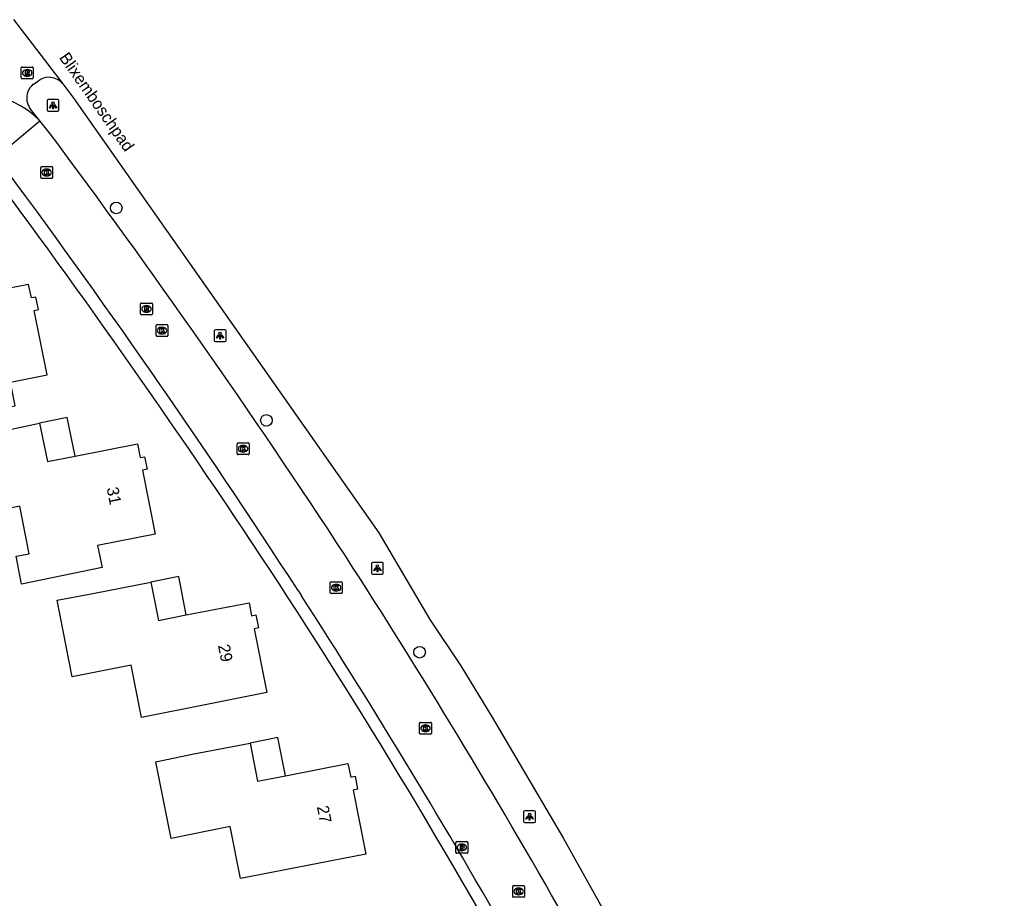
# Model space of a CAD drawing. Extents: x 159628 to 160723, y 388176 to 389416.
# Drawn here: x 160613.8 to 160696.7, y 388586.9 to 388661.2 of the extents above; entities that cross this region are included whole.
import ezdxf

# ---------------------------------------------------------------- set-up
doc = ezdxf.new("R2010")
doc.units = 0
for name, color, linetype in [('IMGEO_Boom', 7, 'Continuous'), ('IMGEO_Brandkraan', 7, 'Continuous'), ('IMGEO_Fietspad_gesloten', 7, 'Continuous'), ('IMGEO_Fietspad_open', 7, 'Continuous'), ('IMGEO_Kolk', 7, 'Continuous'), ('IMGEO_Lichtpunt', 7, 'Continuous'), ('IMGEO_Openbare_ruimte_label', 7, 'Continuous'), ('IMGEO_Pand', 7, 'Continuous'), ('IMGEO_Pand_nummerreeks', 7, 'Continuous'), ('IMGEO_Pand_overbouw', 7, 'Continuous'), ('IMGEO_Rijbaan_lokaal_open', 7, 'Continuous'), ('IMGEO_Rioolput', 7, 'Continuous'), ('IMGEO_Voetpad_open', 7, 'Continuous')]:
    doc.layers.add(name, color=color, linetype=linetype)

msp = doc.modelspace()

# ---------------------------------------------------------------- linework, layer by layer
at = {"layer": 'IMGEO_Boom'}
for centre in [(160621.931, 388645.272), (160634.62, 388627.316), (160647.568, 388607.711)]:
    msp.add_circle(centre, 0.489, dxfattribs=at)
at = {"layer": 'IMGEO_Brandkraan'}
for p, q in [((160650.633, 388590.785), (160650.633, 388591.637)), ((160650.708, 388591.711), (160651.56, 388591.711)), ((160651.634, 388591.637), (160651.634, 388590.785)), ((160651.144, 388590.931), (160651.119, 388590.931)), ((160651.121, 388591.491), (160651.146, 388591.491)), ((160651.56, 388590.711), (160650.708, 388590.711))]:
    msp.add_line(p, q, dxfattribs=at)
for points in [[(160650.633, 388590.785), (160650.633, 388591.637)], [(160650.708, 388591.711), (160651.56, 388591.711)], [(160651.634, 388591.637), (160651.634, 388590.785)], [(160650.981, 388591.411), (160650.981, 388591.011), (160651.194, 388591.011)], [(160651.212, 388591.411), (160650.981, 388591.411)], [(160651.16, 388591.33), (160651.106, 388591.33), (160651.106, 388591.254)], [(160651.106, 388591.254), (160651.159, 388591.254)], [(160651.168, 388591.178), (160651.106, 388591.178), (160651.106, 388591.097)], [(160651.106, 388591.097), (160651.168, 388591.097)], [(160651.56, 388590.711), (160650.708, 388590.711)]]:
    msp.add_lwpolyline(points, dxfattribs=at)
for centre, radius, start, end in [((160650.71, 388591.635), 0.0765, 91.55205, 178.44795), ((160650.71, 388591.635), 0.0765, 91.55205, 178.44795), ((160651.558, 388591.635), 0.0765, 1.55205, 88.44795), ((160651.558, 388591.635), 0.0765, 1.55205, 88.44795), ((160651.161, 388591.292), 0.0379, 267.82845, 90.93552), ((160651.169, 388591.137), 0.0404, 269.87594, 90.50774), ((160651.2, 388591.262), 0.251, 268.66757, 293.53466), ((160651.216, 388591.266), 0.145, 59.4692, 91.53667), ((160651.241, 388591.313), 0.0922, 285.51372, 58.15012), ((160651.246, 388591.121), 0.105, 301.31148, 78.98903), ((160650.71, 388590.787), 0.0765, 181.55205, 268.44795), ((160650.71, 388590.787), 0.0765, 181.55205, 268.44795), ((160651.558, 388590.787), 0.0765, 271.55205, 358.44795), ((160651.558, 388590.787), 0.0765, 271.55205, 358.44795)]:
    msp.add_arc(centre, radius, start, end, dxfattribs=at)
for centre, major_axis, ratio, start_param, end_param in [((160651.12, 388591.211), (-0.387, 0.002), 0.722429, 4.712389, 7.853982), ((160651.145, 388591.211), (-0.39, 0.002), 0.717154, 1.570796, 4.712389)]:
    msp.add_ellipse(centre, major_axis=major_axis, ratio=ratio, start_param=start_param, end_param=end_param, dxfattribs=at)
at = {"layer": 'IMGEO_Fietspad_gesloten'}
for points in [[(160613.259, 388661.194), (160617.404, 388655.77)], [(160617.404, 388655.77), (160618.348, 388654.532), (160644.11, 388617.805), (160648.439, 388610.479), (160651.047, 388606.571), (160653.72, 388602.158), (160659.741, 388591.966), (160665.707, 388581.259), (160668.575, 388576.406), (160671.137, 388571.605), (160689.88, 388531.792), (160696.248, 388516.722), (160696.73, 388515.639)]]:
    msp.add_lwpolyline(points, dxfattribs=at)
at = {"layer": 'IMGEO_Fietspad_open'}
for points in [[(160614.945, 388655.743), (160615.331, 388656.003)], [(160615.474, 388652.64), (160614.696, 388653.623)]]:
    msp.add_lwpolyline(points, dxfattribs=at)
for centre, radius, start, end in [((160615.852, 388654.562), 1.489, 127.52045, 219.08183), ((160616.249, 388654.833), 1.487, 39.04601, 128.12802)]:
    msp.add_arc(centre, radius, start, end, dxfattribs=at)
at = {"layer": 'IMGEO_Kolk'}
for p, q in [((160615.552, 388647.844), (160615.552, 388648.696)), ((160615.627, 388648.77), (160616.479, 388648.77)), ((160616.04, 388648.55), (160616.065, 388648.55)), ((160616.553, 388648.696), (160616.553, 388647.844)), ((160616.479, 388647.77), (160615.627, 388647.77)), ((160616.063, 388647.99), (160616.038, 388647.99)), ((160625.297, 388634.482), (160625.297, 388635.334)), ((160625.372, 388635.408), (160626.224, 388635.408)), ((160625.785, 388635.188), (160625.81, 388635.188)), ((160626.298, 388635.334), (160626.298, 388634.482)), ((160626.224, 388634.408), (160625.372, 388634.408)), ((160625.808, 388634.628), (160625.783, 388634.628)), ((160632.149, 388624.488), (160632.149, 388625.34)), ((160632.224, 388625.414), (160633.076, 388625.414)), ((160632.637, 388625.194), (160632.662, 388625.194)), ((160633.15, 388625.34), (160633.15, 388624.488)), ((160633.076, 388624.414), (160632.224, 388624.414)), ((160632.66, 388624.634), (160632.635, 388624.634)), ((160640.021, 388612.744), (160640.021, 388613.596)), ((160640.096, 388613.67), (160640.948, 388613.67)), ((160640.509, 388613.45), (160640.534, 388613.45)), ((160641.022, 388613.596), (160641.022, 388612.744)), ((160640.948, 388612.67), (160640.096, 388612.67)), ((160640.532, 388612.89), (160640.507, 388612.89)), ((160647.562, 388600.854), (160647.562, 388601.706)), ((160647.637, 388601.78), (160648.489, 388601.78)), ((160648.563, 388601.706), (160648.563, 388600.854)), ((160648.489, 388600.78), (160647.637, 388600.78)), ((160648.073, 388601), (160648.048, 388601)), ((160648.05, 388601.56), (160648.075, 388601.56)), ((160655.434, 388587.066), (160655.434, 388587.918)), ((160655.509, 388587.992), (160656.361, 388587.992)), ((160655.922, 388587.772), (160655.947, 388587.772)), ((160656.435, 388587.918), (160656.435, 388587.066)), ((160656.361, 388586.992), (160655.509, 388586.992)), ((160655.945, 388587.212), (160655.92, 388587.212))]:
    msp.add_line(p, q, dxfattribs=at)
for points in [[(160615.552, 388647.844), (160615.552, 388648.696)], [(160615.627, 388648.77), (160616.479, 388648.77)], [(160615.873, 388648.47), (160615.996, 388648.47), (160615.996, 388648.319), (160616.126, 388648.47), (160616.29, 388648.47), (160616.144, 388648.319), (160616.297, 388648.07), (160616.145, 388648.07), (160616.06, 388648.234), (160615.996, 388648.167), (160615.996, 388648.07), (160615.873, 388648.07), (160615.873, 388648.47)], [(160616.553, 388648.696), (160616.553, 388647.844)], [(160616.479, 388647.77), (160615.627, 388647.77)], [(160625.297, 388634.482), (160625.297, 388635.334)], [(160625.372, 388635.408), (160626.224, 388635.408)], [(160625.618, 388635.108), (160625.741, 388635.108), (160625.741, 388634.957), (160625.871, 388635.108), (160626.035, 388635.108), (160625.889, 388634.957), (160626.042, 388634.708), (160625.89, 388634.708), (160625.805, 388634.872), (160625.741, 388634.805), (160625.741, 388634.708), (160625.618, 388634.708), (160625.618, 388635.108)], [(160626.298, 388635.334), (160626.298, 388634.482)], [(160626.224, 388634.408), (160625.372, 388634.408)], [(160632.149, 388624.488), (160632.149, 388625.34)], [(160632.224, 388625.414), (160633.076, 388625.414)], [(160632.47, 388625.114), (160632.593, 388625.114), (160632.593, 388624.963), (160632.723, 388625.114), (160632.887, 388625.114), (160632.741, 388624.963), (160632.894, 388624.714), (160632.742, 388624.714), (160632.657, 388624.878), (160632.593, 388624.811), (160632.593, 388624.714), (160632.47, 388624.714), (160632.47, 388625.114)], [(160633.15, 388625.34), (160633.15, 388624.488)], [(160633.076, 388624.414), (160632.224, 388624.414)], [(160640.021, 388612.744), (160640.021, 388613.596)], [(160640.096, 388613.67), (160640.948, 388613.67)], [(160640.342, 388613.37), (160640.465, 388613.37), (160640.465, 388613.219), (160640.595, 388613.37), (160640.759, 388613.37), (160640.613, 388613.219), (160640.766, 388612.97), (160640.614, 388612.97), (160640.529, 388613.134), (160640.465, 388613.067), (160640.465, 388612.97), (160640.342, 388612.97), (160640.342, 388613.37)], [(160641.022, 388613.596), (160641.022, 388612.744)], [(160640.948, 388612.67), (160640.096, 388612.67)], [(160647.562, 388600.854), (160647.562, 388601.706)], [(160647.637, 388601.78), (160648.489, 388601.78)], [(160648.563, 388601.706), (160648.563, 388600.854)], [(160648.489, 388600.78), (160647.637, 388600.78)], [(160647.883, 388601.48), (160648.006, 388601.48), (160648.006, 388601.329), (160648.136, 388601.48), (160648.3, 388601.48), (160648.154, 388601.329), (160648.307, 388601.08), (160648.155, 388601.08), (160648.07, 388601.244), (160648.006, 388601.177), (160648.006, 388601.08), (160647.883, 388601.08), (160647.883, 388601.48)], [(160655.434, 388587.066), (160655.434, 388587.918)], [(160655.509, 388587.992), (160656.361, 388587.992)], [(160655.755, 388587.692), (160655.878, 388587.692), (160655.878, 388587.541), (160656.008, 388587.692), (160656.172, 388587.692), (160656.026, 388587.541), (160656.179, 388587.292), (160656.027, 388587.292), (160655.942, 388587.456), (160655.878, 388587.389), (160655.878, 388587.292), (160655.755, 388587.292), (160655.755, 388587.692)], [(160656.435, 388587.918), (160656.435, 388587.066)], [(160656.361, 388586.992), (160655.509, 388586.992)]]:
    msp.add_lwpolyline(points, dxfattribs=at)
for centre, start, end in [((160615.629, 388648.694), 91.55205, 178.44795), ((160615.629, 388648.694), 91.55205, 178.44795), ((160616.477, 388648.694), 1.55205, 88.44795), ((160616.477, 388648.694), 1.55205, 88.44795), ((160615.629, 388647.846), 181.55205, 268.44795), ((160615.629, 388647.846), 181.55205, 268.44795), ((160616.477, 388647.846), 271.55205, 358.44795), ((160616.477, 388647.846), 271.55205, 358.44795), ((160625.374, 388635.332), 91.55205, 178.44795), ((160625.374, 388635.332), 91.55205, 178.44795), ((160626.222, 388635.332), 1.55205, 88.44795), ((160626.222, 388635.332), 1.55205, 88.44795), ((160625.374, 388634.484), 181.55205, 268.44795), ((160625.374, 388634.484), 181.55205, 268.44795), ((160626.222, 388634.484), 271.55205, 358.44795), ((160626.222, 388634.484), 271.55205, 358.44795), ((160632.226, 388625.338), 91.55205, 178.44795), ((160632.226, 388625.338), 91.55205, 178.44795), ((160633.074, 388625.338), 1.55205, 88.44795), ((160633.074, 388625.338), 1.55205, 88.44795), ((160632.226, 388624.49), 181.55205, 268.44795), ((160632.226, 388624.49), 181.55205, 268.44795), ((160633.074, 388624.49), 271.55205, 358.44795), ((160633.074, 388624.49), 271.55205, 358.44795), ((160640.098, 388613.594), 91.55205, 178.44795), ((160640.098, 388613.594), 91.55205, 178.44795), ((160640.946, 388613.594), 1.55205, 88.44795), ((160640.946, 388613.594), 1.55205, 88.44795), ((160640.098, 388612.746), 181.55205, 268.44795), ((160640.098, 388612.746), 181.55205, 268.44795), ((160640.946, 388612.746), 271.55205, 358.44795), ((160640.946, 388612.746), 271.55205, 358.44795), ((160647.639, 388601.704), 91.55205, 178.44795), ((160647.639, 388601.704), 91.55205, 178.44795), ((160648.487, 388601.704), 1.55205, 88.44795), ((160648.487, 388601.704), 1.55205, 88.44795), ((160647.639, 388600.856), 181.55205, 268.44795), ((160647.639, 388600.856), 181.55205, 268.44795), ((160648.487, 388600.856), 271.55205, 358.44795), ((160648.487, 388600.856), 271.55205, 358.44795), ((160655.511, 388587.916), 91.55205, 178.44795), ((160655.511, 388587.916), 91.55205, 178.44795), ((160656.359, 388587.916), 1.55205, 88.44795), ((160656.359, 388587.916), 1.55205, 88.44795), ((160655.511, 388587.068), 181.55205, 268.44795), ((160655.511, 388587.068), 181.55205, 268.44795), ((160656.359, 388587.068), 271.55205, 358.44795), ((160656.359, 388587.068), 271.55205, 358.44795)]:
    msp.add_arc(centre, 0.0765, start, end, dxfattribs=at)
for centre, major_axis, ratio, start_param, end_param in [((160616.039, 388648.27), (-0.387, 0.002), 0.722429, 4.712389, 7.853982), ((160616.064, 388648.27), (-0.39, 0.002), 0.717154, 1.570796, 4.712389), ((160625.784, 388634.908), (-0.387, 0.002), 0.722429, 4.712389, 7.853982), ((160625.809, 388634.908), (-0.39, 0.002), 0.717154, 1.570796, 4.712389), ((160632.636, 388624.914), (-0.387, 0.002), 0.722429, 4.712389, 7.853982), ((160632.661, 388624.914), (-0.39, 0.002), 0.717154, 1.570796, 4.712389), ((160640.508, 388613.17), (-0.387, 0.002), 0.722429, 4.712389, 7.853982), ((160640.533, 388613.17), (-0.39, 0.002), 0.717154, 1.570796, 4.712389), ((160648.049, 388601.28), (-0.387, 0.002), 0.722429, 4.712389, 7.853982), ((160648.074, 388601.28), (-0.39, 0.002), 0.717154, 1.570796, 4.712389), ((160655.921, 388587.492), (-0.387, 0.002), 0.722429, 4.712389, 7.853982), ((160655.946, 388587.492), (-0.39, 0.002), 0.717154, 1.570796, 4.712389)]:
    msp.add_ellipse(centre, major_axis=major_axis, ratio=ratio, start_param=start_param, end_param=end_param, dxfattribs=at)
at = {"layer": 'IMGEO_Lichtpunt'}
for p, q in [((160616.093, 388654.344), (160616.093, 388653.537)), ((160616.093, 388654.344), (160616.093, 388653.537)), ((160616.995, 388654.439), (160616.187, 388654.439)), ((160616.995, 388654.439), (160616.187, 388654.439)), ((160617.089, 388653.537), (160617.089, 388654.344)), ((160617.089, 388653.537), (160617.089, 388654.344)), ((160616.187, 388653.443), (160616.995, 388653.443)), ((160616.187, 388653.443), (160616.995, 388653.443)), ((160630.212, 388634.884), (160630.212, 388634.077)), ((160630.212, 388634.884), (160630.212, 388634.077)), ((160631.114, 388634.979), (160630.306, 388634.979)), ((160631.114, 388634.979), (160630.306, 388634.979)), ((160631.208, 388634.077), (160631.208, 388634.884)), ((160631.208, 388634.077), (160631.208, 388634.884)), ((160630.306, 388633.983), (160631.114, 388633.983)), ((160630.306, 388633.983), (160631.114, 388633.983)), ((160643.505, 388615.206), (160643.505, 388614.399)), ((160643.505, 388615.206), (160643.505, 388614.399)), ((160644.407, 388615.301), (160643.599, 388615.301)), ((160644.407, 388615.301), (160643.599, 388615.301)), ((160644.501, 388614.399), (160644.501, 388615.206)), ((160644.501, 388614.399), (160644.501, 388615.206)), ((160643.599, 388614.305), (160644.407, 388614.305)), ((160643.599, 388614.305), (160644.407, 388614.305)), ((160656.359, 388594.213), (160656.359, 388593.406)), ((160656.359, 388594.213), (160656.359, 388593.406)), ((160657.261, 388594.308), (160656.453, 388594.308)), ((160657.261, 388594.308), (160656.453, 388594.308)), ((160657.355, 388593.406), (160657.355, 388594.213)), ((160657.355, 388593.406), (160657.355, 388594.213)), ((160656.453, 388593.312), (160657.261, 388593.312)), ((160656.453, 388593.312), (160657.261, 388593.312))]:
    msp.add_line(p, q, dxfattribs=at)
for points in [[(160616.467, 388654.008), (160616.506, 388653.98), (160616.318, 388653.718), (160616.28, 388653.745), (160616.467, 388654.008)], [(160616.569, 388653.96), (160616.616, 388653.96), (160616.616, 388653.638), (160616.569, 388653.638), (160616.569, 388653.96)], [(160616.679, 388653.98), (160616.717, 388654.007), (160616.904, 388653.745), (160616.865, 388653.717), (160616.679, 388653.98)], [(160630.586, 388634.548), (160630.625, 388634.52), (160630.437, 388634.258), (160630.399, 388634.285), (160630.586, 388634.548)], [(160630.688, 388634.5), (160630.735, 388634.5), (160630.735, 388634.178), (160630.688, 388634.178), (160630.688, 388634.5)], [(160630.798, 388634.52), (160630.836, 388634.547), (160631.023, 388634.285), (160630.984, 388634.257), (160630.798, 388634.52)], [(160643.879, 388614.87), (160643.918, 388614.842), (160643.73, 388614.58), (160643.692, 388614.607), (160643.879, 388614.87)], [(160644.091, 388614.842), (160644.129, 388614.869), (160644.316, 388614.607), (160644.277, 388614.579), (160644.091, 388614.842)], [(160643.981, 388614.822), (160644.028, 388614.822), (160644.028, 388614.5), (160643.981, 388614.5), (160643.981, 388614.822)], [(160656.733, 388593.877), (160656.772, 388593.849), (160656.584, 388593.587), (160656.546, 388593.614), (160656.733, 388593.877)], [(160656.835, 388593.829), (160656.882, 388593.829), (160656.882, 388593.507), (160656.835, 388593.507), (160656.835, 388593.829)], [(160656.945, 388593.849), (160656.983, 388593.876), (160657.17, 388593.614), (160657.131, 388593.586), (160656.945, 388593.849)]]:
    msp.add_lwpolyline(points, dxfattribs=at)
for centre in [(160616.592, 388654.142), (160630.711, 388634.682), (160644.004, 388615.004), (160656.858, 388594.011)]:
    msp.add_circle(centre, 0.0994, dxfattribs=at)
for centre, start, end in [((160616.187, 388654.344), 90, 180), ((160616.187, 388654.344), 90, 180), ((160616.995, 388654.344), 0, 90), ((160616.995, 388654.344), 0, 90), ((160616.187, 388653.537), 180, 270), ((160616.187, 388653.537), 180, 270), ((160616.995, 388653.537), 270, 0), ((160616.995, 388653.537), 270, 360), ((160630.306, 388634.884), 90, 180), ((160630.306, 388634.884), 90, 180), ((160631.114, 388634.884), 0, 90), ((160631.114, 388634.884), 0, 90), ((160630.306, 388634.077), 180, 270), ((160630.306, 388634.077), 180, 270), ((160631.114, 388634.077), 270, 0), ((160631.114, 388634.077), 270, 360), ((160643.599, 388615.206), 90, 180), ((160643.599, 388615.206), 90, 180), ((160644.407, 388615.206), 0, 90), ((160644.407, 388615.206), 0, 90), ((160643.599, 388614.399), 180, 270), ((160643.599, 388614.399), 180, 270), ((160644.407, 388614.399), 270, 0), ((160644.407, 388614.399), 270, 360), ((160656.453, 388594.213), 90, 180), ((160656.453, 388594.213), 90, 180), ((160657.261, 388594.213), 0, 90), ((160657.261, 388594.213), 0, 90), ((160656.453, 388593.406), 180, 270), ((160656.453, 388593.406), 180, 270), ((160657.261, 388593.406), 270, 0), ((160657.261, 388593.406), 270, 360)]:
    msp.add_arc(centre, 0.0946, start, end, dxfattribs=at)
at = {"layer": 'IMGEO_Pand'}
for points in [[(160614.999, 388636.594), (160615.365, 388636.673), (160615.144, 388637.737), (160614.775, 388637.674), (160614.522, 388638.804), (160609.244, 388637.781), (160606.901, 388637.327), (160606.254, 388640.563), (160601.352, 388639.583), (160598.319, 388638.991), (160599.287, 388634.086), (160599.594, 388632.531), (160604.617, 388633.547), (160605.513, 388629.115), (160607.124, 388629.422), (160607.508, 388627.411), (160613.392, 388628.534), (160612.988, 388630.557), (160616.082, 388631.175), (160614.999, 388636.594)], [(160613.927, 388613.479), (160613.464, 388615.824), (160614.579, 388616.044), (160613.789, 388620.051), (160608.777, 388619.063), (160607.509, 388625.539), (160610.549, 388626.042), (160615.439, 388627.083), (160616.13, 388623.839), (160618.458, 388624.293), (160623.727, 388625.32), (160623.951, 388624.172), (160624.324, 388624.244), (160624.533, 388623.175), (160624.16, 388623.102), (160625.214, 388617.694), (160620.353, 388616.747), (160620.737, 388614.881), (160613.927, 388613.479)], [(160616.928, 388612.11), (160619.954, 388612.682), (160624.86, 388613.645), (160625.498, 388610.397), (160627.853, 388610.86), (160633.152, 388611.901), (160633.366, 388610.775), (160633.713, 388610.866), (160633.95, 388609.774), (160633.575, 388609.693), (160634.645, 388604.299), (160629.74, 388603.331), (160624.076, 388602.2), (160623.204, 388606.621), (160618.193, 388605.633), (160616.928, 388612.11)], [(160631.553, 388592.976), (160626.562, 388591.974), (160625.29, 388598.453), (160628.337, 388599.099), (160633.248, 388600.037), (160633.865, 388596.809), (160636.233, 388597.269), (160641.506, 388598.292), (160641.744, 388597.146), (160642.123, 388597.227), (160642.305, 388596.131), (160641.952, 388596.055), (160643.01, 388590.64), (160638.103, 388589.685), (160632.437, 388588.572), (160631.553, 388592.976)]]:
    msp.add_lwpolyline(points, dxfattribs=at)
at = {"layer": 'IMGEO_Pand_overbouw'}
for points in [[(160618.458, 388624.293), (160617.794, 388627.55), (160615.439, 388627.083), (160616.13, 388623.839)], [(160627.853, 388610.86), (160627.215, 388614.108), (160624.86, 388613.645), (160625.498, 388610.397)], [(160633.248, 388600.037), (160633.865, 388596.809), (160636.233, 388597.269), (160635.573, 388600.509)]]:
    msp.add_lwpolyline(points, close=True, dxfattribs=at)
at = {"layer": 'IMGEO_Rijbaan_lokaal_open'}
for points in [[(160611.811, 388649.592), (160615.474, 388652.64)], [(160616.249, 388651.661), (160615.474, 388652.64)], [(160637.292, 388612.941), (160637.599, 388612.467)]]:
    msp.add_lwpolyline(points, dxfattribs=at)
for centre, radius, start, end in [((160609.493, 388646.587), 8.51, 45.34229, 118.19385), ((160059.624, 388235.617), 694.927, 33.172403, 36.775977), ((160052.092, 388233.274), 697.572, 32.974798, 36.641837), ((160131.083, 388286.162), 607.466, 29.493811, 32.869723), ((160131.433, 388286.289), 602.16, 29.499633, 32.79812)]:
    msp.add_arc(centre, radius, start, end, dxfattribs=at)
at = {"layer": 'IMGEO_Rioolput'}
for p, q in [((160613.983, 388657.188), (160614.835, 388657.188)), ((160613.908, 388656.262), (160613.908, 388657.114)), ((160614.419, 388656.408), (160614.394, 388656.408)), ((160614.396, 388656.968), (160614.421, 388656.968)), ((160614.909, 388657.114), (160614.909, 388656.262)), ((160614.835, 388656.188), (160613.983, 388656.188)), ((160623.985, 388636.307), (160623.985, 388637.159)), ((160624.06, 388637.233), (160624.912, 388637.233)), ((160624.496, 388636.453), (160624.471, 388636.453)), ((160624.473, 388637.013), (160624.498, 388637.013)), ((160624.986, 388637.159), (160624.986, 388636.307)), ((160624.912, 388636.233), (160624.06, 388636.233))]:
    msp.add_line(p, q, dxfattribs=at)
for points in [[(160613.983, 388657.188), (160614.835, 388657.188)], [(160613.908, 388656.262), (160613.908, 388657.114)], [(160614.497, 388656.886), (160614.245, 388656.888), (160614.245, 388656.488)], [(160614.245, 388656.488), (160614.369, 388656.488), (160614.369, 388656.65), (160614.38, 388656.65)], [(160614.423, 388656.807), (160614.369, 388656.807), (160614.369, 388656.726)], [(160614.369, 388656.726), (160614.421, 388656.726)], [(160614.427, 388656.621), (160614.498, 388656.488), (160614.638, 388656.488), (160614.573, 388656.614)], [(160614.909, 388657.114), (160614.909, 388656.262)], [(160614.835, 388656.188), (160613.983, 388656.188)], [(160623.985, 388636.307), (160623.985, 388637.159)], [(160624.06, 388637.233), (160624.912, 388637.233)], [(160624.574, 388636.931), (160624.322, 388636.933), (160624.322, 388636.533)], [(160624.322, 388636.533), (160624.446, 388636.533), (160624.446, 388636.695), (160624.457, 388636.695)], [(160624.5, 388636.852), (160624.446, 388636.852), (160624.446, 388636.771)], [(160624.446, 388636.771), (160624.498, 388636.771)], [(160624.504, 388636.666), (160624.575, 388636.533), (160624.715, 388636.533), (160624.65, 388636.659)], [(160624.986, 388637.159), (160624.986, 388636.307)], [(160624.912, 388636.233), (160624.06, 388636.233)]]:
    msp.add_lwpolyline(points, dxfattribs=at)
for centre, radius, start, end in [((160613.985, 388657.112), 0.0765, 91.55205, 178.44795), ((160613.985, 388657.112), 0.0765, 91.55205, 178.44795), ((160614.833, 388657.112), 0.0765, 1.55205, 88.44795), ((160614.833, 388657.112), 0.0765, 1.55205, 88.44795), ((160614.379, 388656.597), 0.0533, 26.02933, 88.69889), ((160614.405, 388656.915), 0.19, 274.7715, 282.96867), ((160614.429, 388656.711), 0.0964, 77.00612, 93.18647), ((160614.443, 388656.768), 0.0378, 276.66336, 79.67722), ((160614.496, 388656.776), 0.109, 350.36119, 89.41601), ((160614.494, 388656.776), 0.112, 277.58423, 350.98172), ((160614.478, 388656.561), 0.108, 29.51342, 73.79051), ((160613.985, 388656.264), 0.0765, 181.55205, 268.44795), ((160613.985, 388656.264), 0.0765, 181.55205, 268.44795), ((160614.833, 388656.264), 0.0765, 271.55205, 358.44795), ((160614.833, 388656.264), 0.0765, 271.55205, 358.44795), ((160624.062, 388637.157), 0.0765, 91.55205, 178.44795), ((160624.062, 388637.157), 0.0765, 91.55205, 178.44795), ((160624.456, 388636.642), 0.0533, 26.02933, 88.69889), ((160624.482, 388636.96), 0.19, 274.7715, 282.96867), ((160624.506, 388636.756), 0.0964, 77.00612, 93.18647), ((160624.52, 388636.813), 0.0378, 276.66336, 79.67722), ((160624.573, 388636.821), 0.109, 350.36119, 89.41601), ((160624.571, 388636.821), 0.112, 277.58423, 350.98172), ((160624.555, 388636.606), 0.108, 29.51342, 73.79051), ((160624.91, 388637.157), 0.0765, 1.55205, 88.44795), ((160624.91, 388637.157), 0.0765, 1.55205, 88.44795), ((160624.062, 388636.309), 0.0765, 181.55205, 268.44795), ((160624.062, 388636.309), 0.0765, 181.55205, 268.44795), ((160624.91, 388636.309), 0.0765, 271.55205, 358.44795), ((160624.91, 388636.309), 0.0765, 271.55205, 358.44795)]:
    msp.add_arc(centre, radius, start, end, dxfattribs=at)
for centre, major_axis, ratio, start_param, end_param in [((160614.395, 388656.688), (-0.387, 0.002), 0.722429, 4.712389, 7.853982), ((160614.42, 388656.688), (-0.39, 0.002), 0.717154, 1.570796, 4.712389), ((160624.472, 388636.733), (-0.387, 0.002), 0.722429, 4.712389, 7.853982), ((160624.497, 388636.733), (-0.39, 0.002), 0.717154, 1.570796, 4.712389)]:
    msp.add_ellipse(centre, major_axis=major_axis, ratio=ratio, start_param=start_param, end_param=end_param, dxfattribs=at)
at = {"layer": 'IMGEO_Voetpad_open'}
for centre, radius, start, end in [((160024.287, 388212.221), 731.333, 33.174997, 36.616009), ((160136.463, 388289.389), 595.224, 28.296796, 32.866288)]:
    msp.add_arc(centre, radius, start, end, dxfattribs=at)

# ---------------------------------------------------------------- texts
at = {"layer": 'IMGEO_Openbare_ruimte_label'}
msp.add_text('Blixemboschpad', height=1, rotation=305.02487, dxfattribs=at).set_placement((160617.065, 388657.975))
at = {"layer": 'IMGEO_Pand_nummerreeks'}
for s, rotation, p in [('31', 281.0337, (160621.115, 388621.579)), ('29', 281.11123, (160630.521, 388608.278)), ('27', 281.11974, (160638.88, 388594.644))]:
    msp.add_text(s, height=1, rotation=rotation, dxfattribs=at).set_placement(p)

doc.saveas('drawing.dxf')
